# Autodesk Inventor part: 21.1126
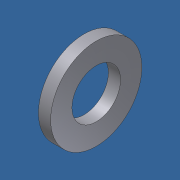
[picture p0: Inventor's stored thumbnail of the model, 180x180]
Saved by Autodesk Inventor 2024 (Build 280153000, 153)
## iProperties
Created: 2006-02
Part Number: 21.1126
Material: Steel, Mild
Description: M6 ROUND WASHER DIN 125-1A
Document SubType Name: Modeling
Standard: DIN 125
Designer: Andy Moles
Standards Organization: DIN
Language: en-US
Size Designation: A 6.4
Categories: <MemberInstance><Categories><Category DisplayName="Fasteners" InternalName="e4da775c-781d-43d5-af7c-5136215cf5a6" Mnemonic="FSTN"><Category DisplayName="Washers
Density: 7.86 g/cm^3
Vendor: S
Mass: 1.01774 g
Surface Area: 2.54343 cm^2
Volume: 0.129484 cm^3
Appearance: Zinc
Author: Andy Moles
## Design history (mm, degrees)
workaxis "Work Axis1"
workplane "Work Plane1"
body "Solid1"
sketch "Sketch"
  geometry: C1 r 6 at (0, 0); C2 r 3.2 at (0, 0); 1 further point
  constraints: 2 centre point, 2 coincident
  dimensions: "d0" = 6.4 diameter of C2 (= SD1); "d1" = 12 diameter of C1 (= SD2)
extrude "Body" new body sketch "Sketch" distance "d2" = 1.6 (= SD); taper "d3" = 0 deg
other parameters: "SD1" = 6.4 [user parameter; used in 1 equation term], "SD2" = 12 [user parameter; used in 1 equation term], "SD" = 1.6 [user parameter; used in 1 equation term], "d4" = 0, "d5" = 0, "d6" = 0, "d7" = 0, "NND" = 6 [user parameter]
